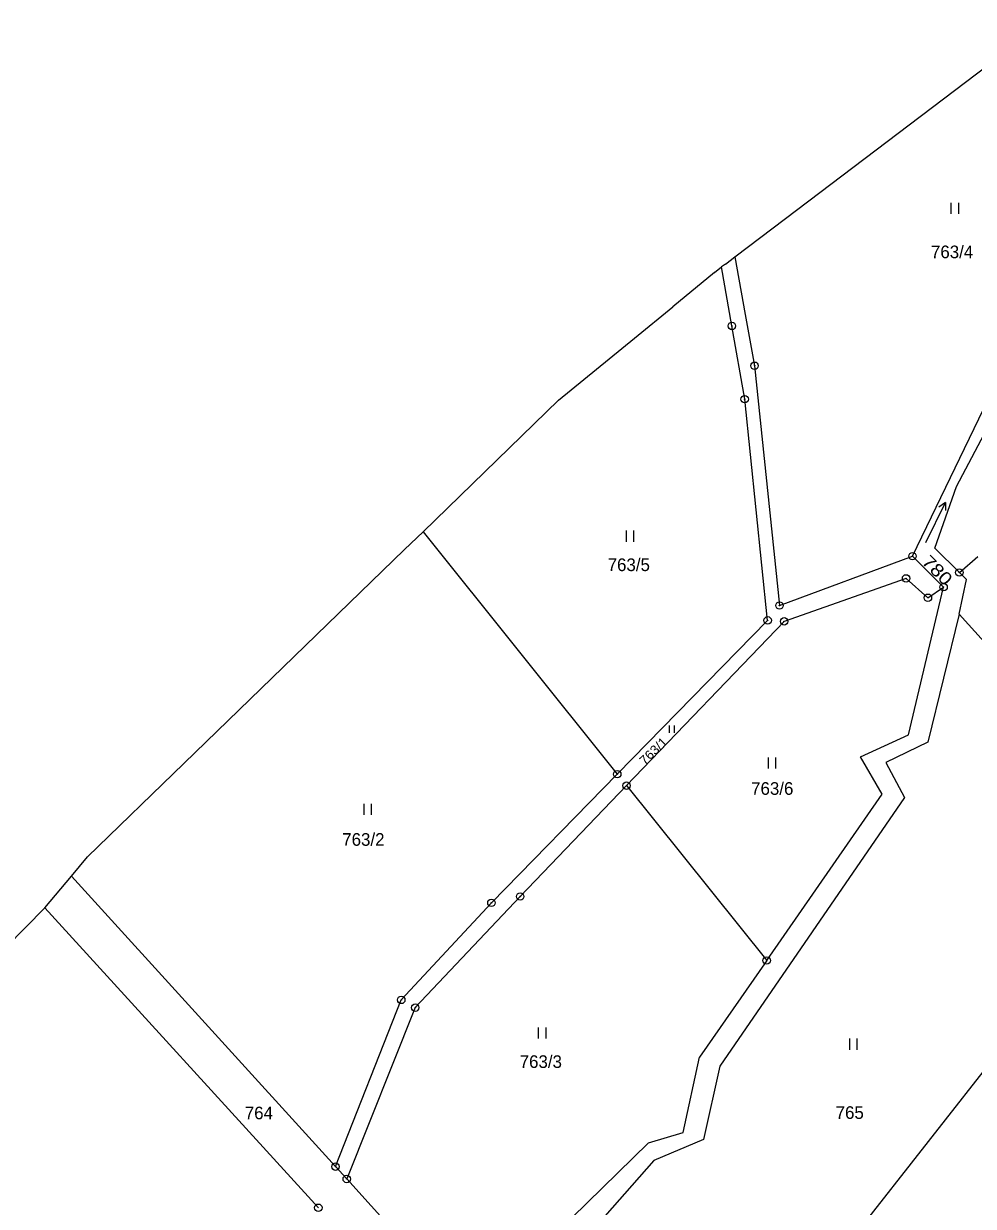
# Model space of a CAD drawing. Extents: x -727701 to -724405, y -960481 to -957284.
# Drawn here: x -727182.9 to -727055.1, y -958207.9 to -958048.7 of the extents above; entities that cross this region are included whole.
import ezdxf
from ezdxf.enums import TextEntityAlignment as Align

# ---------------------------------------------------------------- set-up
doc = ezdxf.new("R2010")
doc.units = 0
doc.header["$LTSCALE"] = 0.68
for name, color, linetype, lineweight in [('1', 7, 'Continuous', 25), ('3', 7, 'Continuous', 25), ('8', 7, 'Continuous', 25)]:
    doc.layers.add(name, color=color, linetype=linetype, lineweight=lineweight)
doc.layers.add('2', color=7, linetype='Continuous')

msp = doc.modelspace()

# ---------------------------------------------------------------- linework, layer by layer
at = {"layer": '1'}
for p, q in [((-727080.39, -958074.95), (-727045.8, -958048.73)), ((-727057.36, -958111.03), (-727036.02, -958070.29)), ((-727087.2, -958080.12), (-727085.8, -958087.87)), ((-727089.94, -958082.2), (-727095.57, -958086.83)), ((-727089.94, -958082.2), (-727088.99, -958081.48)), ((-727088.47, -958081.08), (-727088.99, -958081.48)), ((-727087.6, -958089.41), (-727088.99, -958081.48)), ((-727100.72, -958091.05), (-727095.57, -958086.83)), ((-727085.8, -958087.87), (-727084.55, -958094.77)), ((-727085.88, -958099.27), (-727087.6, -958089.41)), ((-727110.92, -958099.42), (-727100.72, -958091.05)), ((-727084.55, -958094.77), (-727081.2, -958127.04)), ((-727063.3, -958120.4), (-727051.8, -958096.6)), ((-727110.92, -958099.42), (-727129.17, -958117.11)), ((-727082.79, -958129.04), (-727085.88, -958099.27)), ((-727060.31, -958119.33), (-727057.36, -958111.03)), ((-727129.17, -958117.11), (-727131.65, -958119.51)), ((-727129.17, -958117.11), (-727103.03, -958149.73)), ((-727131.65, -958119.51), (-727161.36, -958148.32)), ((-727081.2, -958127.04), (-727063.3, -958120.4)), ((-727059.11, -958124.57), (-727063.3, -958120.4)), ((-727060.31, -958119.33), (-727056.99, -958122.6)), ((-727056.99, -958122.6), (-727054.52, -958120.45)), ((-727064.16, -958123.39), (-727080.57, -958129.17)), ((-727061.22, -958125.99), (-727064.16, -958123.39)), ((-727057.02, -958128.2), (-727056.04, -958123.54)), ((-727056.04, -958123.54), (-727056.99, -958122.6)), ((-727063.82, -958144.44), (-727059.11, -958124.57)), ((-727061.22, -958125.99), (-727059.11, -958124.57)), ((-727057.02, -958128.2), (-727061.25, -958145.43)), ((-727029.5, -958158.7), (-727057.02, -958128.2)), ((-727082.79, -958129.04), (-727103.03, -958149.73)), ((-727101.78, -958151.28), (-727080.57, -958129.17)), ((-727070.29, -958147.41), (-727063.82, -958144.44)), ((-727061.25, -958145.43), (-727066.87, -958148.18)), ((-727067.37, -958152.45), (-727070.29, -958147.41)), ((-727174.31, -958160.88), (-727161.36, -958148.32)), ((-727066.87, -958148.18), (-727064.38, -958152.86)), ((-727103.03, -958149.73), (-727119.97, -958167.05)), ((-727116.09, -958166.2), (-727101.78, -958151.28)), ((-727101.78, -958151.28), (-727082.92, -958174.81)), ((-727082.92, -958174.81), (-727067.37, -958152.45)), ((-727064.38, -958152.86), (-727089.24, -958189.04)), ((-727029.5, -958158.7), (-727100.91, -958249.86)), ((-727176.46, -958163.45), (-727174.31, -958160.88)), ((-727180.05, -958167.72), (-727176.46, -958163.45)), ((-727176.46, -958163.45), (-727140.95, -958202.56)), ((-727116.09, -958166.2), (-727130.22, -958181.16)), ((-727180.05, -958167.72), (-727185.28, -958173.04)), ((-727180.05, -958167.72), (-727143.26, -958208.09)), ((-727132.1, -958180.12), (-727119.97, -958167.05)), ((-727082.92, -958174.81), (-727091.97, -958187.82)), ((-727140.95, -958202.56), (-727132.1, -958180.12)), ((-727130.22, -958181.16), (-727139.44, -958204.22)), ((-727094.17, -958197.96), (-727091.97, -958187.82)), ((-727089.24, -958189.04), (-727091.42, -958198.89)), ((-727098.83, -958199.36), (-727094.17, -958197.96)), ((-727122.68, -958222.68), (-727098.83, -958199.36)), ((-727091.42, -958198.89), (-727098.09, -958201.72)), ((-727098.09, -958201.72), (-727119.62, -958226.1)), ((-727140.95, -958202.56), (-727139.44, -958204.22)), ((-727122.68, -958222.68), (-727139.44, -958204.22))]:
    msp.add_line(p, q, dxfattribs=at)
msp.add_lwpolyline([(-727088.47, -958081.08), (-727087.2, -958080.12), (-727080.39, -958074.95)], dxfattribs=at)
at = {"layer": '3'}
for p, q in [((-727058.071, -958074.33), (-727058.071, -958072.83)), ((-727057.07, -958074.33), (-727057.07, -958072.83)), ((-727058.86, -958113.162), (-727058.837, -958114.26)), ((-727101.781, -958118.45), (-727101.781, -958116.95)), ((-727100.78, -958118.45), (-727100.78, -958116.95)), ((-727095.982, -958144.19), (-727095.982, -958143.185)), ((-727095.312, -958144.19), (-727095.312, -958143.185)), ((-727082.681, -958148.98), (-727082.681, -958147.48)), ((-727081.68, -958148.98), (-727081.68, -958147.48)), ((-727137.091, -958155.21), (-727137.091, -958153.71)), ((-727136.09, -958155.21), (-727136.09, -958153.71)), ((-727113.621, -958185.32), (-727113.621, -958183.82)), ((-727112.62, -958185.32), (-727112.62, -958183.82)), ((-727071.751, -958186.82), (-727071.751, -958185.32)), ((-727070.75, -958186.82), (-727070.75, -958185.32))]:
    msp.add_line(p, q, dxfattribs=at)
msp.add_lwpolyline([(-727061.49, -958118.555), (-727058.86, -958113.162), (-727059.739, -958113.82)], dxfattribs=at)
at = {"layer": '8'}
for centre, radius in [((-727087.6, -958089.4099), 0.5), ((-727087.6, -958089.4099), 0.0303), ((-727084.55, -958094.7699), 0.5), ((-727084.55, -958094.7699), 0.0303), ((-727085.88, -958099.2699), 0.5), ((-727085.88, -958099.2699), 0.0303), ((-727063.3, -958120.3999), 0.5), ((-727063.3, -958120.3999), 0.0303), ((-727056.99, -958122.5999), 0.5), ((-727064.16, -958123.3899), 0.5), ((-727064.16, -958123.3899), 0.0303), ((-727056.99, -958122.5999), 0.0303), ((-727059.11, -958124.5699), 0.5), ((-727059.11, -958124.5699), 0.0303), ((-727081.2, -958127.0399), 0.5), ((-727081.2, -958127.0399), 0.0303), ((-727061.22, -958125.9899), 0.5), ((-727061.22, -958125.9899), 0.0303), ((-727082.79, -958129.0399), 0.5), ((-727080.57, -958129.1699), 0.5), ((-727082.79, -958129.0399), 0.0303), ((-727080.57, -958129.1699), 0.0303), ((-727103.03, -958149.7299), 0.5), ((-727103.03, -958149.7299), 0.0303), ((-727101.78, -958151.2799), 0.5), ((-727101.78, -958151.2799), 0.0303), ((-727119.97, -958167.0499), 0.5), ((-727116.09, -958166.1999), 0.5), ((-727116.09, -958166.1999), 0.0303), ((-727119.97, -958167.0499), 0.0303), ((-727082.92, -958174.8099), 0.5), ((-727082.92, -958174.8099), 0.0303), ((-727132.1, -958180.1199), 0.5), ((-727132.1, -958180.1199), 0.0303), ((-727130.22, -958181.1599), 0.5), ((-727130.22, -958181.1599), 0.0303), ((-727140.95, -958202.5599), 0.5), ((-727140.95, -958202.5599), 0.0303), ((-727139.44, -958204.2199), 0.5), ((-727139.44, -958204.2199), 0.0303), ((-727143.26, -958208.0899), 0.5)]:
    msp.add_circle(centre, radius, dxfattribs=at)

# ---------------------------------------------------------------- texts
at = {"layer": '2'}
for s, p in [('763/4', (-727060.81, -958080.295)), ('764', (-727153.16, -958196.185)), ('765', (-727073.64, -958196.135))]:
    msp.add_text(s, height=1.7, dxfattribs=at).set_placement(p)
for s, p in [('763/5', (-727101.48, -958122.405)), ('763/6', (-727082.17, -958152.515)), ('763/2', (-727137.2, -958159.375)), ('763/3', (-727113.32, -958189.275))]:
    msp.add_text(s, height=1.7, dxfattribs=at).set_placement(p, align=Align.CENTER)
for s, height, rotation, width, p in [('780', 1.7, 315, 1.2, (-727062.17, -958121.28)), ('763/1', 1.2, 44, 1.1, (-727099.351, -958148.585))]:
    msp.add_text(s, height=height, rotation=rotation, dxfattribs=dict(at, width=width)).set_placement(p)

doc.saveas('drawing.dxf')
